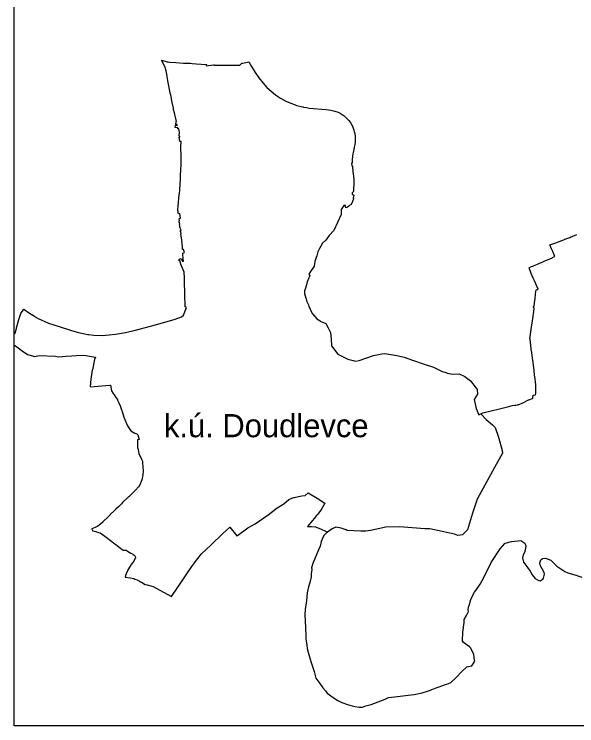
# Model space of a CAD drawing. Extents: x -823399 to -812899, y -1074543 to -1067118.
# Drawn here: x -823399 to -820967, y -1074543 to -1071469 of the extents above; entities that cross this region are included whole.
import ezdxf

# ---------------------------------------------------------------- set-up
doc = ezdxf.new("R2010")
doc.units = 0
for name, color, linetype in [('formát', 7, 'Continuous'), ('Hranice katastrálního území_bez dotčení', 7, 'Continuous'), ('Hranice katastrálního území_dotčené', 7, 'Continuous'), ('Název KU_bez dotčení', 7, 'Continuous')]:
    doc.layers.add(name, color=color, linetype=linetype)

msp = doc.modelspace()

# ---------------------------------------------------------------- linework, layer by layer
at = {"layer": 'formát'}
msp.add_lwpolyline([(-823398.7, -1067117.7), (-818148.7, -1067117.7), (-818148.7, -1074542.7), (-823398.7, -1074542.7)], close=True, dxfattribs=at)
at = {"layer": 'Hranice katastrálního území_bez dotčení'}
for points in [[(-823398.7, -1072898.3), (-823393.2, -1072901.2), (-823364.9, -1072922.9), (-823341.7, -1072938.2), (-823310.2, -1072946.9), (-823291.1, -1072943.2), (-823220.7, -1072946.2), (-823207.5, -1072948.4), (-823175.2, -1072946.2), (-823149.9, -1072944.4), (-823108.8, -1072941.3), (-823088.5, -1072942.8), (-823047.4, -1072949.9), (-823051.4, -1072960.8), (-823060.9, -1073005), (-823061.3, -1073006.9), (-823067.2, -1073045.3), (-823070.6, -1073078.5), (-822986.1, -1073071.9)], [(-822986.1, -1073071.9), (-822983.2, -1073071.9), (-822977.5, -1073095.8), (-822970.5, -1073106.8), (-822966.6, -1073113.1), (-822959, -1073124.1), (-822952.9, -1073132.7), (-822951.6, -1073135.5), (-822945.9, -1073147.8), (-822940.2, -1073159.9), (-822936.2, -1073173), (-822932.7, -1073184.3), (-822924.2, -1073209.9), (-822909, -1073246.8), (-822895, -1073269.1), (-822877.7, -1073278.5), (-822869.1, -1073280.8), (-822863.9, -1073286.4), (-822858.2, -1073306), (-822863.8, -1073306.3), (-822865.1, -1073310.5), (-822866, -1073323.4), (-822865.2, -1073341.1), (-822863.5, -1073348.7), (-822859.5, -1073366.6), (-822848.4, -1073391.6), (-822844.7, -1073399.9), (-822844.3, -1073406.1), (-822842, -1073440.9), (-822842.7, -1073458.7), (-822843, -1073460.8), (-822843.6, -1073464.7), (-822845.1, -1073475.4), (-822846.8, -1073480.1), (-822852.7, -1073495.2), (-822854.1, -1073498.8), (-822861.4, -1073510.4), (-822875, -1073525.3), (-822877.6, -1073528.1), (-822878.4, -1073528.9), (-822903.7, -1073553.2), (-822904.2, -1073553.6), (-822907.1, -1073556.2), (-822907.7, -1073556.8), (-822930.1, -1073578.8), (-822935.5, -1073584), (-822948.5, -1073596.6), (-822959.6, -1073607.3), (-822965.1, -1073612.7), (-822968.6, -1073616), (-822982.3, -1073629.2), (-822983.4, -1073630.2), (-822984.2, -1073631), (-822995.9, -1073643), (-823012.3, -1073659.2), (-823015, -1073661.8), (-823015.9, -1073662.6), (-823024.3, -1073670.2), (-823036.7, -1073679.8), (-823048.2, -1073686.5), (-823063.8, -1073691.9), (-823062.8, -1073694), (-823060.6, -1073698.9), (-823059.8, -1073700.6), (-823046.6, -1073703.8), (-823038.8, -1073705.7), (-823026.6, -1073708.6), (-823006.6, -1073724.1), (-822977.1, -1073747), (-822962.7, -1073758.1), (-822959.9, -1073760.1), (-822939.5, -1073775.4), (-822932.6, -1073780.6), (-822930.7, -1073782), (-822928.5, -1073783.6), (-822915.2, -1073784.4), (-822911.8, -1073786.6), (-822909, -1073788.9), (-822894.5, -1073796.5), (-822887.3, -1073800.2), (-822883.9, -1073802.4), (-822880.6, -1073805), (-822878.8, -1073806.9), (-822877.7, -1073808), (-822877.3, -1073808.8), (-822877.1, -1073809), (-822875.7, -1073811.3), (-822874.6, -1073814.3), (-822874.6, -1073814.4), (-822874.2, -1073815.4), (-822872.8, -1073816.9), (-822877.2, -1073822.1), (-822882.1, -1073831.5), (-822888.2, -1073840.2), (-822891.9, -1073844.6), (-822894.3, -1073847.5), (-822894.9, -1073848.4), (-822897.3, -1073852.7), (-822907.1, -1073869.5), (-822907.4, -1073870), (-822915.2, -1073886.9)], [(-821381.8, -1073194.8), (-821358.1, -1073219.2), (-821330.7, -1073242.8), (-821319.2, -1073254.6), (-821306, -1073295.9), (-821290.2, -1073352.8), (-821289.2, -1073356.1), (-821288.1, -1073360.2), (-821288.3, -1073365), (-821322.9, -1073426.2), (-821397.3, -1073563.4), (-821418.5, -1073624.1), (-821439.8, -1073696.3), (-821460.4, -1073717.4), (-821480.6, -1073720.3), (-821495.7, -1073715.2), (-821602.2, -1073692.2), (-821623.9, -1073691.3), (-821733.1, -1073682.9), (-821793, -1073684.5), (-821837.9, -1073694.4), (-821858.8, -1073699.1), (-821878.8, -1073702.4), (-821899.9, -1073701.6), (-821959.1, -1073699.5), (-821963.2, -1073696.3), (-821986.1, -1073688.7), (-822008.5, -1073684), (-822024, -1073692.4), (-822044.3, -1073706.1)], [(-822915.2, -1073886.9), (-822917.4, -1073893.4), (-822918.7, -1073901.1), (-822898.1, -1073903.7), (-822882.1, -1073907.1), (-822877.6, -1073908.9), (-822867.7, -1073912.9), (-822856.8, -1073918.5), (-822852.8, -1073920.6), (-822848.6, -1073922.8), (-822832.4, -1073931.8), (-822824.7, -1073933.9), (-822797.4, -1073941.2), (-822753.7, -1073965.4), (-822718.4, -1073984.4), (-822672.7, -1073916.7), (-822661, -1073899.3), (-822655.5, -1073891.2), (-822649.3, -1073882), (-822630.3, -1073853.9), (-822618.7, -1073837.7), (-822607.1, -1073821.4), (-822605.7, -1073819.6), (-822588.7, -1073799.2), (-822549.1, -1073762.1), (-822531.1, -1073745.1), (-822513.8, -1073728.9), (-822498, -1073714.1), (-822467.4, -1073685.4), (-822466.1, -1073684.1), (-822460.3, -1073691.4), (-822441.8, -1073715), (-822436.2, -1073722.1), (-822434.1, -1073720.6), (-822388.6, -1073687.4), (-822357.5, -1073670), (-822319.6, -1073644.2), (-822301.4, -1073630.7), (-822262.8, -1073600.6), (-822234, -1073583.2), (-822211.9, -1073565.6), (-822198.6, -1073559.1), (-822189.7, -1073556.3), (-822189, -1073556.1), (-822170.3, -1073551.8), (-822155.9, -1073549.1), (-822141.6, -1073547.8), (-822128.8, -1073536.8), (-822089.8, -1073560.1), (-822055.4, -1073580.6), (-822069.2, -1073604.5), (-822073.8, -1073610.6), (-822088, -1073629.4), (-822089.5, -1073631.2), (-822092, -1073634.3), (-822102.5, -1073646.8), (-822131.1, -1073681.2), (-822113.7, -1073682.4), (-822096.1, -1073683.3), (-822072, -1073693.1), (-822052.8, -1073702.1), (-822044.3, -1073706.1)], [(-822044.3, -1073706.1), (-822047.8, -1073708.3), (-822060.7, -1073720.3), (-822071.4, -1073746.5), (-822076.8, -1073767.3), (-822083.1, -1073782), (-822107.9, -1073842), (-822113.2, -1073860.6), (-822113, -1073867.8), (-822114.8, -1073885.6), (-822115.8, -1073898.8), (-822121.6, -1073923.7), (-822126.8, -1073941.8), (-822131.3, -1073961.6), (-822133.1, -1073968.2), (-822135.5, -1074001.9), (-822141.5, -1074040.8), (-822142.3, -1074061.4), (-822139.4, -1074118.8), (-822139.3, -1074127.4), (-822138.6, -1074145.9), (-822137.9, -1074167.6), (-822134.1, -1074194.5), (-822132.1, -1074208.2), (-822128.3, -1074224.6), (-822117.1, -1074264.6), (-822115.6, -1074269.2), (-822102.2, -1074308.7), (-822094.6, -1074336.5), (-822077.2, -1074360.7), (-822064.2, -1074378.3), (-822053.5, -1074391.9), (-822045.3, -1074401.2), (-822020.4, -1074420.3), (-821999.3, -1074434.2), (-821982.5, -1074442.7), (-821958.8, -1074450.5), (-821937.5, -1074456.1), (-821925.8, -1074459.2), (-821907, -1074462.6), (-821893.6, -1074461.8), (-821879.2, -1074456.7), (-821856.1, -1074450.2), (-821814.3, -1074435), (-821794.7, -1074427.2), (-821781.6, -1074420.7), (-821741.9, -1074416.1), (-821708, -1074412), (-821695.3, -1074409.8), (-821670.3, -1074406.9), (-821636, -1074400.6), (-821608.2, -1074391.2), (-821589.3, -1074384.5), (-821582.5, -1074381.9), (-821575.4, -1074379.2), (-821562.4, -1074374.6), (-821550.6, -1074370.4), (-821539.3, -1074366.4), (-821529.1, -1074363.2), (-821514.8, -1074357), (-821511.7, -1074355.5), (-821488, -1074334.2), (-821466.1, -1074309.8), (-821442, -1074287.8), (-821435.8, -1074286.2), (-821421, -1074283.2), (-821407.3, -1074263.9), (-821409.6, -1074259.6), (-821410.4, -1074250.9), (-821410.6, -1074248.4), (-821412, -1074233.6), (-821426.9, -1074205.8), (-821430.2, -1074202.1), (-821457.4, -1074183.2), (-821461.3, -1074175.2), (-821459.1, -1074138.2), (-821454.4, -1074096.1), (-821453.4, -1074082.9), (-821444.1, -1074066.2), (-821437.6, -1074055.4), (-821435.4, -1074048.8), (-821436.6, -1074040.6), (-821436.7, -1074039.8), (-821435, -1074030.2), (-821434.8, -1074029.4), (-821434.1, -1074026.2), (-821432.3, -1074023.5), (-821424.5, -1073996.8), (-821418.1, -1073980.8), (-821409.1, -1073966.1), (-821403.4, -1073958), (-821384.1, -1073931.1), (-821367.1, -1073898.6), (-821337.2, -1073837.7), (-821298, -1073777.8), (-821278.7, -1073754.6), (-821277, -1073753.6), (-821249.3, -1073746), (-821209.5, -1073742.9), (-821204.1, -1073744.8), (-821191.5, -1073753.9)], [(-821191.5, -1073753.9), (-821187.3, -1073765.1), (-821190.5, -1073784.3), (-821193, -1073793.7), (-821199, -1073804), (-821201.1, -1073817.5), (-821196.8, -1073836.5), (-821191.1, -1073843.6), (-821168.3, -1073874.8), (-821159.8, -1073891), (-821147.6, -1073906), (-821136.7, -1073911.9), (-821130.6, -1073914.9), (-821125.1, -1073916.1), (-821113.5, -1073909.1), (-821111.2, -1073905.2), (-821107, -1073887.7), (-821107.8, -1073881.1), (-821116.3, -1073864.1), (-821125.4, -1073848.5), (-821126.8, -1073838.6), (-821122.8, -1073825.3), (-821115.4, -1073820), (-821102.7, -1073818.3), (-821079.5, -1073827.9), (-821053.3, -1073852.6), (-821018.7, -1073876.8), (-821006, -1073881.8), (-820971.1, -1073892.1), (-820945.1, -1073901.2)]]:
    msp.add_lwpolyline(points, dxfattribs=at)
at = {"layer": 'Hranice katastrálního území_dotčené'}
for points in [[(-822745.6, -1071698.8), (-822758.1, -1071674.3), (-822759.5, -1071671.6), (-822761.6, -1071667.5), (-822746.4, -1071671.7), (-822739.3, -1071673.7), (-822732.8, -1071674.8), (-822726.2, -1071675.9), (-822700, -1071677.9), (-822666.9, -1071680.2), (-822637.2, -1071680.6), (-822629.1, -1071681.2), (-822612.5, -1071682.6), (-822567.9, -1071685.6), (-822568.5, -1071691), (-822537.4, -1071686.6), (-822534.2, -1071686.8), (-822533.2, -1071688.9), (-822423.9, -1071688.7), (-822421.4, -1071686.6), (-822414.4, -1071680.7), (-822411.5, -1071680.1), (-822404.6, -1071678.8), (-822384.6, -1071673.9), (-822372.9, -1071694.1), (-822357, -1071720.3), (-822341.2, -1071743.4), (-822323.2, -1071767), (-822306.3, -1071785.4), (-822269, -1071816.9), (-822247.7, -1071831.9), (-822224.8, -1071844), (-822217.7, -1071847.1), (-822216.5, -1071847.6), (-822214.3, -1071848.5), (-822202.4, -1071853.6), (-822187.7, -1071859.2), (-822178.6, -1071862.6), (-822151.6, -1071869.4), (-822148.5, -1071870), (-822134.7, -1071872.3), (-822124.5, -1071873.9), (-822050, -1071880), (-822029.8, -1071882.8), (-822013, -1071886.8), (-821998.8, -1071892.2), (-821985, -1071899.1), (-821973.2, -1071907.4), (-821968.6, -1071911.4), (-821963.2, -1071916), (-821952.7, -1071927.3), (-821944.4, -1071939.1), (-821936.9, -1071952.3), (-821931.6, -1071965.5), (-821927.7, -1071979.3), (-821924.9, -1071994.2), (-821924.5, -1072009.1), (-821924.5, -1072009.3), (-821925.6, -1072022.1), (-821926.8, -1072032.1), (-821928.6, -1072042.3), (-821932.8, -1072061.1), (-821933.3, -1072064), (-821934.8, -1072072.9), (-821936.1, -1072081.1), (-821937.4, -1072099.3), (-821937.3, -1072112.2), (-821938.8, -1072112.2), (-821940.3, -1072112.3), (-821939.9, -1072124.1), (-821936.1, -1072125.1), (-821936.3, -1072130.1), (-821934.9, -1072147.9), (-821931.4, -1072180), (-821930.9, -1072204.8), (-821931.8, -1072220.6), (-821932.3, -1072234.2), (-821934.9, -1072238.1), (-821938.6, -1072240.7), (-821938.2, -1072246.5), (-821938.1, -1072247.7), (-821932, -1072248.5), (-821930.7, -1072250.1), (-821931, -1072251.6), (-821933.6, -1072262.8), (-821933.7, -1072262.8), (-821934.8, -1072263.3), (-821931.5, -1072264.1), (-821932.8, -1072268), (-821935, -1072273.9), (-821937.7, -1072281.4), (-821944.1, -1072291.4), (-821947.5, -1072293.8), (-821950.5, -1072296.4), (-821952.2, -1072297.9), (-821953.7, -1072299.2), (-821958.2, -1072301.8), (-821960, -1072302.8), (-821961.3, -1072303.5), (-821966, -1072304.7), (-821966, -1072304.1)], [(-822669.3, -1072505.8), (-822669.3, -1072505.1), (-822669.6, -1072500.7), (-822662.3, -1072497.7), (-822667.6, -1072484.6), (-822670.6, -1072485.8), (-822671.1, -1072477.5), (-822671.2, -1072476.5), (-822671.7, -1072471.2), (-822672.6, -1072462.8), (-822672.9, -1072459.8), (-822673.8, -1072450.8), (-822673.4, -1072450.7), (-822674.3, -1072444.7), (-822674.6, -1072442.5), (-822675.2, -1072438.8), (-822675, -1072438.8), (-822675.9, -1072429.9), (-822676.4, -1072430), (-822677.3, -1072424), (-822678.1, -1072418.1), (-822677.1, -1072418), (-822678, -1072409), (-822679.4, -1072409.2), (-822680.3, -1072403.1), (-822678.6, -1072402.9), (-822677, -1072402.6), (-822677.9, -1072396.8), (-822679.4, -1072397.1), (-822680.7, -1072388.3), (-822682.3, -1072388.5), (-822683.2, -1072382.4), (-822684, -1072376.6), (-822682.4, -1072376.4), (-822683.7, -1072367.6), (-822685.2, -1072367.8), (-822686.1, -1072361.3), (-822684.7, -1072361.1), (-822684.8, -1072360.5), (-822686.1, -1072351.1), (-822680, -1072350.3), (-822683, -1072330), (-822689.1, -1072330.9), (-822689.8, -1072326.2), (-822690.7, -1072319.9), (-822690.9, -1072318.1), (-822691.5, -1072313.8), (-822691.8, -1072312.3), (-822690.3, -1072298.4), (-822685.1, -1072248.3), (-822684.4, -1072241.3), (-822683.2, -1072229.9), (-822683, -1072226.3), (-822680.6, -1072181.9), (-822679.3, -1072157.9), (-822678.8, -1072147.6), (-822676.7, -1072110.1), (-822676.7, -1072106.2), (-822676.7, -1072105.5), (-822676.8, -1072092.2), (-822676.8, -1072086.8), (-822676.8, -1072082.1), (-822678.9, -1072043.3), (-822679, -1072042.5), (-822676.6, -1072018.7), (-822682.8, -1072018.1), (-822685.7, -1071999.6), (-822683.3, -1071999.9), (-822683, -1071995.8), (-822685.5, -1071995.6), (-822683.8, -1071977.6), (-822687, -1071964), (-822691.4, -1071963.6), (-822692.1, -1071959.5), (-822702.7, -1071958.4), (-822702.7, -1071958), (-822701.8, -1071949.1), (-822701.7, -1071947.9), (-822693.8, -1071948.7), (-822694.4, -1071944.8), (-822699.2, -1071944.3), (-822699.2, -1071944.6), (-822699.6, -1071944.5), (-822698.4, -1071931.6), (-822697.5, -1071931.7), (-822705, -1071902.5), (-822706.5, -1071895), (-822709.5, -1071880.1), (-822710.2, -1071876.6), (-822710.5, -1071874.9), (-822715.4, -1071850.7), (-822722.1, -1071817.3), (-822722.6, -1071814.8), (-822734, -1071756.2), (-822734.1, -1071755.5), (-822737.7, -1071737.4), (-822739.7, -1071726.9), (-822742.5, -1071712.7), (-822743.4, -1071708.4), (-822744.8, -1071702.1), (-822745.6, -1071698.8)], [(-821966, -1072304.1), (-821966.3, -1072299.3), (-821966.6, -1072295), (-821972.5, -1072293.5), (-821973.4, -1072294.9), (-821984.8, -1072312.1), (-821984.8, -1072334.3), (-822016.8, -1072402.4), (-822036.9, -1072423.9), (-822052.1, -1072444.1), (-822066.2, -1072458.4), (-822079.7, -1072480.5), (-822086.2, -1072494.5), (-822086.7, -1072495.4), (-822090.7, -1072512), (-822093.7, -1072520.2), (-822098.5, -1072533.1), (-822099, -1072536.6), (-822101.7, -1072555.3), (-822101.9, -1072556.8), (-822108, -1072565.9), (-822114.7, -1072575.9), (-822124.8, -1072591.1), (-822121.6, -1072598.6), (-822125.3, -1072607.5), (-822132.3, -1072625.2), (-822136, -1072637.6), (-822141.5, -1072656.1), (-822143.3, -1072663.4), (-822144.2, -1072674.5), (-822138.6, -1072695.7), (-822137.5, -1072698.7), (-822135.1, -1072706.3), (-822134.8, -1072707.3), (-822127.3, -1072724), (-822125.8, -1072729.5), (-822119.6, -1072742.8), (-822116.1, -1072749.9), (-822109.2, -1072763.7), (-822090.7, -1072784), (-822075.9, -1072793), (-822075.9, -1072794.4), (-822051.4, -1072804.3), (-822041.6, -1072823.6), (-822032.1, -1072844.3), (-822028.2, -1072870.5), (-822027, -1072901), (-822000.1, -1072937.7), (-821957.4, -1072959.3), (-821934.2, -1072965.2), (-821922.9, -1072967.8), (-821908, -1072964.1), (-821846.1, -1072942.4), (-821809.4, -1072936), (-821796.2, -1072935.1), (-821745.2, -1072943.7), (-821713.3, -1072950.6), (-821677.4, -1072963.7), (-821627.4, -1072980.5), (-821586.3, -1072992.8), (-821549.3, -1073011.8), (-821538, -1073015.7), (-821526.6, -1073019.7), (-821503.7, -1073023.9), (-821475.6, -1073022.9), (-821451.6, -1073033.5), (-821426.5, -1073052.8), (-821402.4, -1073083.5), (-821397.5, -1073089.8), (-821396, -1073110.7), (-821410.4, -1073133.8), (-821402.5, -1073171.4), (-821391, -1073199.2), (-821381.8, -1073194.8), (-821372.6, -1073190.3), (-821301.8, -1073173.6), (-821260.7, -1073163.1), (-821245.4, -1073159.6), (-821234.8, -1073157.8), (-821230, -1073157.1), (-821224, -1073156), (-821219.9, -1073155.3), (-821216.2, -1073154.7), (-821196.9, -1073145.4), (-821175.7, -1073135.1), (-821174, -1073134.4), (-821158.6, -1073128.2), (-821157.6, -1073127.8), (-821157.2, -1073127.8), (-821156.6, -1073127.8), (-821156.2, -1073114.7), (-821144.9, -1073113.5), (-821144.9, -1073113.4), (-821144.8, -1073106.5), (-821144.7, -1073100), (-821144.6, -1073093.4), (-821144.6, -1073091.4), (-821144.2, -1073069.2), (-821145.3, -1073057.4), (-821146.7, -1073045), (-821149.2, -1073026.2)], [(-821149.2, -1073026.2), (-821151.6, -1073007.5), (-821153.1, -1072995.5), (-821154.6, -1072984.6), (-821156, -1072973.6), (-821158.6, -1072953.9), (-821161.7, -1072930), (-821163.8, -1072916.9), (-821165.9, -1072899.1), (-821169.2, -1072872.3), (-821169.9, -1072871.7), (-821162.4, -1072820.8), (-821159.6, -1072802.2), (-821155.6, -1072774.7), (-821155.3, -1072772.8), (-821155, -1072770.1), (-821154.4, -1072764.6), (-821151.9, -1072740.4), (-821154.7, -1072733.1), (-821153.9, -1072731.9), (-821150.8, -1072730.6), (-821148.1, -1072704.6), (-821147.8, -1072702), (-821147.6, -1072700.2), (-821147.5, -1072699), (-821147, -1072695.4), (-821146.5, -1072690.8), (-821145.9, -1072685.3), (-821145.5, -1072681.1), (-821145, -1072676.1), (-821144.2, -1072668.7), (-821143.2, -1072659.7), (-821137.6, -1072657.4), (-821136.5, -1072657), (-821134.6, -1072656.2), (-821150.5, -1072620.5), (-821155.8, -1072608.7), (-821163.8, -1072588.4), (-821173.5, -1072563.8), (-821162.6, -1072559), (-821157.1, -1072556.6), (-821154.5, -1072555.5), (-821151, -1072554), (-821137.5, -1072548.1), (-821128.8, -1072544.4), (-821120.1, -1072540.6), (-821111.3, -1072536.8), (-821102.6, -1072533.1), (-821093.9, -1072529.3), (-821077, -1072521.9), (-821072.5, -1072520), (-821066.3, -1072517.4), (-821061.3, -1072515.2), (-821064.3, -1072508.3), (-821067.4, -1072501.5), (-821069.3, -1072497.4), (-821070.8, -1072493.7), (-821075.7, -1072482.2), (-821075.9, -1072481.8), (-821083.3, -1072465.4), (-821083.1, -1072465.3), (-821070.3, -1072460.2), (-821069.9, -1072461.2), (-821052.7, -1072454.3), (-821035.6, -1072447.7), (-821034.2, -1072447.2), (-821027.1, -1072444.3), (-821024.2, -1072443.2), (-821020.8, -1072441.8), (-821018.4, -1072440.9), (-821014.3, -1072439.2), (-821012.9, -1072438.6), (-821010, -1072437.5), (-821001.2, -1072434), (-820997.7, -1072432.6), (-820993, -1072430.7), (-820987.4, -1072428.5), (-820983.5, -1072427), (-820981.2, -1072426.1), (-820969.5, -1072421.4), (-820966.4, -1072420.1)], [(-823395.3, -1072848.9), (-823393.2, -1072841.2), (-823389.4, -1072827.1), (-823388.5, -1072823.4), (-823378.4, -1072788.2), (-823370.4, -1072762.2), (-823357.2, -1072742.9), (-823332.8, -1072760.1), (-823311, -1072772.4), (-823308.5, -1072775.7), (-823295.4, -1072783.3), (-823249.9, -1072803.4), (-823200.5, -1072819.4), (-823151.1, -1072835.4), (-823120.7, -1072843.9), (-823080.5, -1072852.3), (-823076, -1072852.5), (-823054.6, -1072855.7), (-823017, -1072856.8), (-822988.8, -1072853.5), (-822960.6, -1072850.2), (-822917.2, -1072843.3), (-822879.8, -1072835.2), (-822788.3, -1072810.5), (-822703.1, -1072785.4), (-822675.8, -1072775.4), (-822667.3, -1072768.4), (-822654.7, -1072735), (-822660.3, -1072732.3), (-822661.5, -1072678.5), (-822662.6, -1072622.3), (-822662.7, -1072619.5), (-822662.8, -1072612.7), (-822663, -1072602.7), (-822664, -1072587.9), (-822664.5, -1072580.2), (-822665.5, -1072580.6), (-822681.4, -1072541.3), (-822680, -1072540.8), (-822683.2, -1072532.6), (-822685.7, -1072533.7), (-822686.6, -1072531.6), (-822684, -1072530.6), (-822685.2, -1072527.3), (-822677.1, -1072524.1), (-822675.9, -1072527), (-822674.2, -1072526.3), (-822673.8, -1072527.4), (-822673.2, -1072528.9), (-822674.8, -1072529.6), (-822671.7, -1072537.4), (-822667.3, -1072535.7), (-822668, -1072525.2), (-822669.3, -1072505.8)]]:
    msp.add_lwpolyline(points, dxfattribs=at)

# ---------------------------------------------------------------- texts
at = {"layer": 'Název KU_bez dotčení'}
msp.add_text('k.ú. Doudlevce', height=100, dxfattribs=at).set_placement((-822751.6, -1073296.1))

doc.saveas('drawing.dxf')
